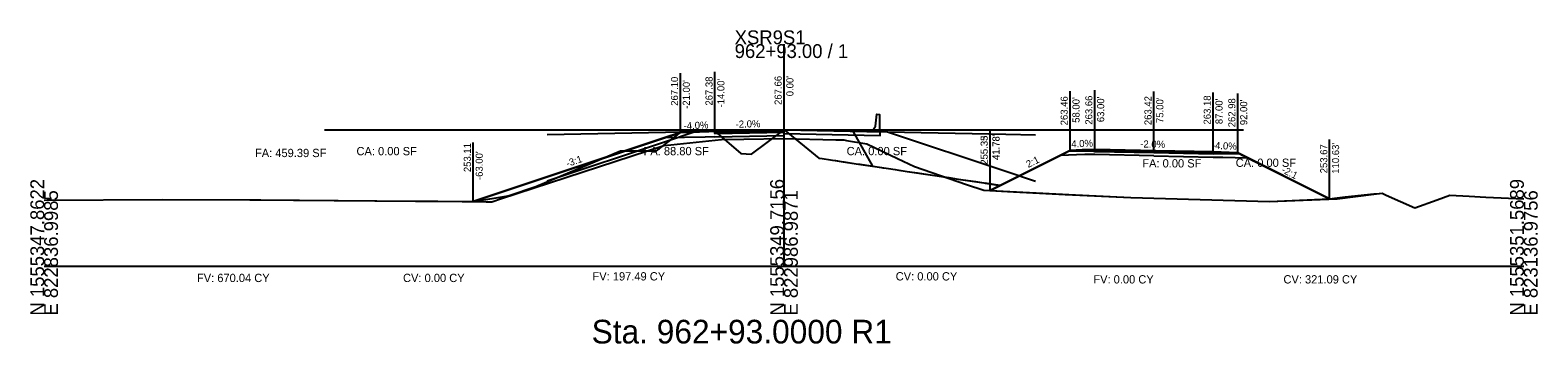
# Model space of a CAD drawing. Extents: x -26 to 823017, y -16 to 1558356.
# Drawn here: x 997.2 to 1302.8, y 1984.3 to 2047.8 of the extents above; entities that cross this region are included whole.
import ezdxf

# ---------------------------------------------------------------- set-up
doc = ezdxf.new("R2010")
doc.units = 0
for name, color, linetype in [('ASPHALT_19MM1', 7, 'Continuous'), ('ASPHALT_9_5MM1', 7, 'Continuous'), ('CONST_DCH', 7, 'Continuous'), ('CONST_LV3', 7, 'Continuous'), ('Default', 7, 'Continuous'), ('Draft_XS_Grid', 7, 'Continuous'), ('Draft_XS_Text', 7, 'Continuous'), ('DTM_CORRIDOR', 7, 'Continuous'), ('DTM_P_FINISHED_GRADE2', 7, 'Continuous'), ('DTM_TEMP_DROP', 7, 'Continuous'), ('DTM_X_GROUND', 7, 'Continuous'), ('PROFILES_DCH_2', 7, 'Continuous'), ('SLOPE_STAKES_FILL', 7, 'Continuous'), ('XS_CELL', 7, 'Continuous'), ('XS_M_SHAPES_EARTHWORK', 7, 'Continuous'), ('XS_P_ASPHALT', 7, 'Continuous'), ('XS_P_CONCRETE', 7, 'Continuous'), ('XS_P_DR_GRAVEL', 7, 'Continuous'), ('XS_P_GROUND', 7, 'Continuous'), ('XS_P_NULL_POINT', 7, 'Continuous'), ('XS_P_SHOULDER', 7, 'Continuous'), ('XS_P_SUBGRADE_GRANULAR', 7, 'Continuous'), ('XS_P_SUBGRADE_MILLING', 7, 'Continuous'), ('XS_P_SUBGRADE_UNDERCUT', 7, 'Continuous'), ('XS_P_TX_CLEARZONE', 7, 'Continuous'), ('XS_P_TX_FS_BS', 7, 'Continuous'), ('XS_SHEET_EW_TX_AREA', 7, 'Continuous'), ('XS_SHEET_EW_TX_VOLUME', 7, 'Continuous')]:
    doc.layers.add(name, color=color, linetype=linetype)

msp = doc.modelspace()

# ---------------------------------------------------------------- linework, layer by layer
at = {"layer": 'ASPHALT_19MM1'}
for points in [[(1150, 2027.37), (1150, 2027.37), (1150, 2027.37), (1136, 2027.09), (1136, 2026.92), (1136, 2026.88), (1150, 2027.16), (1150, 2027.16), (1150, 2027.16)], [(1213, 2023.28), (1225, 2023.04), (1237, 2022.8), (1237, 2023.01), (1225, 2023.25), (1213, 2023.49), (1213, 2023.28)]]:
    msp.add_lwpolyline(points, dxfattribs=at)
at = {"layer": 'ASPHALT_9_5MM1'}
msp.add_lwpolyline([(1150, 2027.66), (1150, 2027.66), (1150, 2027.66), (1136, 2027.38), (1136, 2027.28), (1136, 2027.26), (1150, 2027.54), (1150, 2027.54), (1150, 2027.54)], dxfattribs=at)
at = {"layer": 'CONST_DCH'}
msp.add_lwpolyline([(1213, 2023.49), (1225, 2023.25), (1237, 2023.01), (1237, 2023.18), (1225, 2023.42), (1213, 2023.66), (1213, 2023.49)], dxfattribs=at)
at = {"layer": 'CONST_LV3'}
for points in [[(1056.83, 2027.66), (1059.06, 2027.66), (1067.18, 2027.66), (1070.42, 2027.66), (1077.53, 2027.66), (1081.79, 2027.66), (1087.88, 2027.66), (1092.98, 2027.66), (1098.24, 2027.66), (1102.48, 2027.66), (1108.59, 2027.66), (1115.9, 2027.66), (1118.94, 2027.66), (1127.26, 2027.66), (1129.29, 2027.66), (1130.99, 2027.66), (1139.65, 2027.66), (1140.5, 2027.66), (1150, 2027.66), (1150, 2027.66)], [(1102, 2026.71), (1125.96, 2027.19), (1132, 2027.31), (1146.38, 2027.59), (1150, 2027.67), (1166.77, 2027.33), (1171, 2027.25), (1194.96, 2026.77), (1201, 2026.65)], [(1102, 2017.31), (1125.96, 2025.29), (1132, 2027.31), (1146.38, 2027.59), (1150, 2027.67), (1166.77, 2027.33), (1171, 2027.25), (1194.96, 2019.26), (1201, 2017.25)], [(1150, 2027.66), (1150.59, 2027.66), (1157.45, 2027.66), (1167.49, 2027.66), (1169.32, 2027.66), (1182.33, 2027.66), (1188.64, 2027.66), (1190.46, 2027.66), (1194.72, 2027.66), (1207.35, 2027.66), (1207.96, 2027.66), (1225.43, 2027.66), (1227.27, 2027.66), (1230.92, 2027.66), (1231.99, 2027.66), (1243.17, 2027.67)], [(1150, 2027.67), (1164, 2027.39)], [(1168, 2020.27), (1168, 2020.27), (1164, 2027.39)], [(1191.78, 2015.35), (1207.55, 2023.24), (1208, 2023.46), (1208.15, 2023.47), (1213, 2023.66)], [(1193.78, 2016.35), (1204.72, 2021.82), (1206.38, 2022.65), (1206.57, 2022.74), (1206.59, 2022.75), (1206.9, 2022.91), (1207.36, 2023.14), (1207.36, 2023.14), (1207.37, 2023.14), (1207.4, 2023.16), (1207.4, 2023.16), (1207.42, 2023.17), (1207.55, 2023.24), (1207.57, 2023.24), (1207.58, 2023.25), (1207.66, 2023.29), (1208, 2023.46), (1212.85, 2023.65), (1213, 2023.66), (1213.37, 2023.65), (1225, 2023.42), (1225.37, 2023.41), (1237, 2023.18), (1241.85, 2022.99), (1242, 2022.98), (1242.56, 2022.7), (1242.89, 2022.53), (1243.03, 2022.47), (1243.24, 2022.36), (1243.61, 2022.17), (1244.27, 2021.84), (1246.97, 2020.5), (1260.63, 2013.67), (1262.16, 2013.85), (1263.8, 2014.04), (1269.62, 2014.65), (1270.05, 2014.69), (1271.25, 2014.81), (1272.09, 2014.43), (1277.87, 2011.83), (1282.41, 2013.44), (1284.98, 2014.39), (1288.92, 2014.2), (1292.32, 2014.02), (1300, 2013.65)], [(1242, 2022.98), (1260.69, 2013.64)], [(1000, 2013.38), (1023.98, 2013.54), (1041.69, 2013.47), (1042.31, 2013.47), (1043.91, 2013.45), (1075.27, 2013.21), (1075.69, 2013.21), (1076.41, 2013.2), (1076.55, 2013.2), (1076.76, 2013.2), (1079.81, 2013.17), (1087, 2013.11)]]:
    msp.add_lwpolyline(points, dxfattribs=at)
at = {"layer": 'Default'}
msp.add_lwpolyline([(1150, 2027.54), (1150, 2027.54), (1150, 2027.54), (1136, 2027.26), (1136, 2027.12), (1136, 2027.09), (1150, 2027.37), (1150, 2027.37), (1150, 2027.37)], dxfattribs=at)
at = {"layer": 'DTM_P_FINISHED_GRADE2'}
msp.add_lwpolyline([(1087, 2013.11), (1094.08, 2014.29), (1099.67, 2016.15), (1116.86, 2023.39), (1123.11, 2023.42), (1123.64, 2023.4), (1124.15, 2023.38), (1129, 2027.1), (1134.79, 2027.34), (1136, 2027.38), (1141.26, 2022.83), (1143.41, 2022.73), (1150, 2027.66), (1157.03, 2021.88), (1157.73, 2021.81), (1159.44, 2021.55), (1159.45, 2021.55), (1159.84, 2021.49), (1159.86, 2021.49), (1160.35, 2021.42), (1160.44, 2021.4), (1162, 2021.17), (1162.23, 2021.14), (1164.61, 2020.78), (1165.41, 2020.66), (1169.79, 2020.01), (1170.02, 2019.97), (1170.71, 2019.87), (1171.2, 2019.79), (1172.51, 2019.6), (1173.3, 2019.48), (1174.97, 2019.23), (1177.08, 2018.91), (1180.14, 2018.46), (1180.59, 2018.39), (1181.06, 2018.32), (1183.43, 2017.97), (1185.32, 2017.68), (1188.9, 2017.15), (1190.49, 2016.91), (1190.84, 2016.81), (1193.78, 2016.35), (1193.78, 2016.35)], dxfattribs=at)
at = {"layer": 'DTM_X_GROUND'}
for points in [[(1000, 2013.38), (1023.98, 2013.54), (1041.69, 2013.46), (1042.31, 2013.46), (1043.91, 2013.45), (1075.27, 2013.21), (1075.69, 2013.21), (1076.41, 2013.2), (1076.55, 2013.2), (1076.76, 2013.2), (1079.81, 2013.17), (1087, 2013.11), (1092.95, 2014.1), (1094.02, 2014.28), (1094.08, 2014.29), (1099.67, 2016.15), (1116.86, 2023.39), (1123.11, 2023.42), (1123.64, 2023.4), (1124.15, 2023.38), (1129, 2027.1), (1134.79, 2027.34), (1136, 2027.38), (1141.26, 2022.83), (1143.41, 2022.73), (1150, 2027.66), (1157.03, 2021.88), (1157.73, 2021.81), (1159.44, 2021.55), (1159.45, 2021.55), (1159.84, 2021.49), (1159.86, 2021.49), (1160.35, 2021.42), (1160.44, 2021.4), (1162, 2021.17), (1162.23, 2021.14), (1164.61, 2020.78), (1165.41, 2020.66), (1169.79, 2020.01), (1170.02, 2019.97), (1170.71, 2019.87), (1171.2, 2019.79), (1172.51, 2019.6), (1173.3, 2019.48), (1174.97, 2019.23), (1177.08, 2018.91), (1180.14, 2018.46), (1180.59, 2018.39), (1181.06, 2018.32), (1183.43, 2017.97), (1185.32, 2017.68), (1188.9, 2017.15), (1190.49, 2016.91), (1190.84, 2016.81), (1193.78, 2016.35), (1193.78, 2016.35), (1204.72, 2021.82), (1206.38, 2022.65), (1206.57, 2022.74), (1206.59, 2022.75), (1206.9, 2022.91), (1207.36, 2023.14), (1207.36, 2023.14), (1207.37, 2023.14), (1207.4, 2023.16), (1207.4, 2023.16), (1207.42, 2023.17), (1207.55, 2023.24), (1207.57, 2023.24), (1207.58, 2023.25), (1207.66, 2023.29), (1208, 2023.46), (1212.85, 2023.65), (1213, 2023.66), (1213.37, 2023.65), (1225, 2023.42), (1225.37, 2023.41), (1237, 2023.18), (1241.85, 2022.99), (1242, 2022.98), (1242.56, 2022.7), (1242.89, 2022.53), (1243.03, 2022.47), (1243.24, 2022.36), (1243.61, 2022.17), (1244.27, 2021.84), (1246.97, 2020.5), (1260.63, 2013.67), (1262.16, 2013.85), (1263.8, 2014.04), (1269.62, 2014.65), (1270.05, 2014.69), (1271.25, 2014.81), (1272.09, 2014.43), (1277.87, 2011.83), (1282.41, 2013.44), (1284.98, 2014.39), (1288.92, 2014.2), (1292.32, 2014.02), (1300, 2013.65)], [(1000, 2013.38), (1023.98, 2013.54), (1041.69, 2013.47), (1042.31, 2013.47), (1075.27, 2013.21), (1076.76, 2013.2), (1079.81, 2013.17), (1089.59, 2013.08), (1090.78, 2013.07), (1092.75, 2013.73), (1125.63, 2024.48), (1127.07, 2024.63), (1137.32, 2025.72), (1141.87, 2025.77), (1149.93, 2025.88), (1160.51, 2025.63), (1162.11, 2025.59), (1162.69, 2025.51), (1166.81, 2024.83), (1172.99, 2021.82), (1176.47, 2020.23), (1187, 2016.57), (1190.53, 2015.39), (1196.53, 2015.08), (1207, 2014.55), (1220.32, 2013.96), (1248.41, 2013.13), (1262.16, 2013.67), (1269.62, 2014.61), (1271.25, 2014.81), (1272.09, 2014.43), (1277.87, 2011.83), (1282.41, 2013.44), (1284.98, 2014.39), (1288.92, 2014.2), (1292.32, 2014.02), (1300, 2013.65)], [(1000, 2013.38), (1023.98, 2013.54), (1041.69, 2013.47), (1042.31, 2013.47), (1075.27, 2013.21), (1076.76, 2013.2), (1079.81, 2013.17), (1089.59, 2013.08), (1090.78, 2013.07), (1092.75, 2013.73), (1125.63, 2024.48), (1127.07, 2024.63), (1137.32, 2025.72), (1141.87, 2025.77), (1149.93, 2025.88), (1160.51, 2025.63), (1162.11, 2025.59), (1162.69, 2025.51), (1166.81, 2024.83), (1172.99, 2021.82), (1176.47, 2020.23), (1187, 2016.57), (1190.53, 2015.45), (1191.78, 2015.35), (1206.38, 2022.65), (1206.57, 2022.74), (1206.59, 2022.75), (1207.36, 2023.14), (1207.37, 2023.14), (1207.42, 2023.17), (1207.55, 2023.24), (1208, 2023.46), (1212.85, 2023.65), (1213, 2023.66), (1213.37, 2023.65), (1225, 2023.42), (1225.37, 2023.41), (1237, 2023.18), (1241.85, 2022.99), (1242, 2022.98), (1242.56, 2022.7), (1242.89, 2022.53), (1243.03, 2022.47), (1243.24, 2022.36), (1243.61, 2022.17), (1244.27, 2021.84), (1246.97, 2020.5), (1260.63, 2013.67), (1262.16, 2013.85), (1263.8, 2014.04), (1269.62, 2014.65), (1270.05, 2014.69), (1271.25, 2014.81), (1272.09, 2014.43), (1277.87, 2011.83), (1282.41, 2013.44), (1284.98, 2014.39), (1288.92, 2014.2), (1292.32, 2014.02), (1300, 2013.65)]]:
    msp.add_lwpolyline(points, dxfattribs=at)
at = {"layer": 'XS_CELL'}
for p, q in [((1150, 2000), (1150, 2045)), ((1000, 2000), (1150, 2000)), ((1150, 2000), (1300, 2000))]:
    msp.add_line(p, q, dxfattribs=at)
at = {"layer": 'XS_M_SHAPES_EARTHWORK'}
msp.add_lwpolyline([(1087, 2013.11), (1089.59, 2013.08), (1090.78, 2013.07), (1092.75, 2013.73), (1125.63, 2024.48), (1127.07, 2024.63), (1137.32, 2025.72), (1141.87, 2025.77), (1149.93, 2025.88), (1150, 2025.88), (1150, 2027.16), (1136, 2026.88), (1136, 2026.92), (1136, 2027.09), (1136, 2027.12), (1136, 2027.26), (1136, 2027.28), (1136, 2027.38), (1129, 2027.1), (1125.72, 2026.01)], close=True, dxfattribs=at)
at = {"layer": 'XS_P_CONCRETE'}
for points in [[(1168, 2027.3), (1168, 2027.55), (1168.58, 2028.39), (1168.83, 2030.8), (1169.33, 2030.78), (1169.33, 2027.28), (1168, 2027.3)], [(1150, 2026.91), (1169.5, 2026.52), (1169.5, 2027.27), (1169.33, 2027.28), (1150, 2027.66)]]:
    msp.add_lwpolyline(points, dxfattribs=at)
at = {"layer": 'XS_P_DR_GRAVEL'}
for points in [[(1208.15, 2023.47), (1208, 2023.46), (1207.86, 2023.39), (1207.86, 2023.39), (1212.84, 2023.29), (1213, 2023.28), (1213, 2023.3), (1213, 2023.66), (1208.15, 2023.47)], [(1241.85, 2022.99), (1242, 2022.98), (1242.56, 2022.7), (1242.57, 2022.69), (1242.4, 2022.7), (1237, 2022.8), (1237, 2022.82), (1237, 2023.18), (1241.85, 2022.99)]]:
    msp.add_lwpolyline(points, dxfattribs=at)
at = {"layer": 'XS_P_GROUND'}
for points in [[(1087, 2013.11), (1129, 2027.1)], [(1157.73, 2021.81), (1159.44, 2021.55), (1159.84, 2021.49), (1160.35, 2021.42), (1162, 2021.17), (1164.61, 2020.78), (1168.4, 2020.21), (1169.79, 2020.01), (1170.71, 2019.87), (1172.51, 2019.6), (1174.97, 2019.23), (1180.14, 2018.46), (1181.06, 2018.32), (1185.32, 2017.68), (1190.49, 2016.91), (1190.81, 2016.86)], [(1208, 2023.46), (1191.78, 2015.35)], [(1242, 2022.98), (1260.63, 2013.67)], [(1193.78, 2016.38), (1190.81, 2016.86)]]:
    msp.add_lwpolyline(points, dxfattribs=at)
at = {"layer": 'XS_P_SHOULDER'}
for points in [[(1129, 2027.1), (1136, 2027.38)], [(1208, 2023.46), (1208.15, 2023.47), (1213, 2023.66)], [(1242, 2022.98), (1241.85, 2022.99), (1237, 2023.18)]]:
    msp.add_lwpolyline(points, dxfattribs=at)
at = {"layer": 'XS_P_SUBGRADE_GRANULAR'}
for points in [[(1136, 2026.22), (1134, 2026.18), (1125.72, 2026.01)], [(1136, 2026.22), (1150, 2026.5), (1150, 2026.5)], [(1213, 2022.62), (1211, 2022.66), (1206, 2022.46)], [(1225, 2022.38), (1213, 2022.62)], [(1225, 2022.38), (1237, 2022.14)], [(1237, 2022.14), (1239, 2022.1), (1243.96, 2022)]]:
    msp.add_lwpolyline(points, dxfattribs=at)
at = {"layer": 'XS_P_SUBGRADE_UNDERCUT'}
msp.add_lwpolyline([(1209.11, 2014.47), (1220.32, 2013.96), (1248.41, 2013.13), (1260.63, 2013.67), (1242, 2022.98), (1241.26, 2023.01), (1237, 2023.18), (1225.37, 2023.41), (1213, 2023.66), (1210.42, 2023.56), (1208, 2023.46), (1191.78, 2015.35)], close=True, dxfattribs=at)
at = {"layer": 'XS_P_TX_CLEARZONE'}
for p, q in [((1129, 2027.1), (1129, 2039.1)), ((1136, 2027.38), (1136, 2039.38)), ((1150, 2027.66), (1150, 2039.66)), ((1208, 2023.46), (1208, 2035.46)), ((1213, 2023.66), (1213, 2035.66)), ((1225, 2023.42), (1225, 2035.42)), ((1237, 2023.18), (1237, 2035.18)), ((1242, 2022.98), (1242, 2034.98)), ((1191.78, 2015.35), (1191.78, 2027.35)), ((1191.78, 2015.33), (1191.78, 2027.33)), ((1087, 2013.11), (1087, 2025.11)), ((1260.63, 2013.67), (1260.63, 2025.67))]:
    msp.add_line(p, q, dxfattribs=at)

# ---------------------------------------------------------------- texts
at = {"layer": 'CONST_DCH'}
for p in [(1191.71, 2015.23), (1260.55, 2013.55), (1260.61, 2013.52)]:
    msp.add_text('X', height=0.24, dxfattribs=at).set_placement(p)
at = {"layer": 'Draft_XS_Grid'}
msp.add_text('-', height=0.0001, dxfattribs=at).set_placement((1000, 2000))
at = {"layer": 'Draft_XS_Text'}
msp.add_text('Sta. 962+93.0000 R1', height=4.8, dxfattribs=at).set_placement((1111, 1984.35))
at = {"layer": 'DTM_CORRIDOR'}
for p in [(1212.92, 2023.54), (1224.92, 2023.3), (1236.92, 2023.06)]:
    msp.add_text('X', height=0.24, dxfattribs=at).set_placement(p)
at = {"layer": 'DTM_TEMP_DROP'}
for p in [(1135.92, 2027.26), (1149.92, 2027.54), (1157.65, 2021.69), (1191.71, 2015.21)]:
    msp.add_text('X', height=0.24, dxfattribs=at).set_placement(p)
at = {"layer": 'PROFILES_DCH_2'}
msp.add_text('X', height=0.24, dxfattribs=at).set_placement((1167.92, 2020.15))
at = {"layer": 'SLOPE_STAKES_FILL'}
for p in [(1193.7, 2016.26), (1086.92, 2012.99)]:
    msp.add_text('X', height=0.24, dxfattribs=at).set_placement(p)
at = {"layer": 'XS_CELL'}
for s, p in [('XSR9S1', (1140, 2045)), ('962+93.00 / 1', (1140, 2042.2))]:
    msp.add_text(s, height=2.8, dxfattribs=at).set_placement(p)
for s, p in [('N 1555347.8622', (1000, 1990)), ('N 1555349.7156', (1150, 1990)), ('N 1555351.5689', (1300, 1990)), ('E 822836.9985', (1002.8, 1990)), ('E 822986.9871', (1152.8, 1990)), ('E 823136.9756', (1302.8, 1990))]:
    msp.add_text(s, height=2.8, rotation=90, dxfattribs=at).set_placement(p)
at = {"layer": 'XS_P_ASPHALT'}
for p in [(1191.71, 2015.23), (1260.55, 2013.55)]:
    msp.add_text('X', height=0.24, dxfattribs=at).set_placement(p)
at = {"layer": 'XS_P_NULL_POINT'}
msp.add_text('X', height=0.24, dxfattribs=at).set_placement((1086.92, 2012.99))
at = {"layer": 'XS_P_SHOULDER'}
for p in [(1207.92, 2023.34), (1241.92, 2022.86)]:
    msp.add_text('X', height=0.24, dxfattribs=at).set_placement(p)
at = {"layer": 'XS_P_SUBGRADE_MILLING'}
msp.add_text('X', height=0.24, dxfattribs=at).set_placement((1128.92, 2026.98))
at = {"layer": 'XS_P_TX_CLEARZONE'}
for s, p in [('267.10', (1128.52, 2032.52)), ("-21.00'", (1130.92, 2031.9)), ('267.38', (1135.52, 2032.56)), ("-14.00'", (1137.92, 2032.18)), ('267.66', (1149.52, 2032.69)), ("0.00'", (1151.92, 2034.45)), ('263.46', (1207.52, 2028.56)), ("58.00'", (1209.92, 2029.07)), ('263.66', (1212.52, 2028.69)), ("63.00'", (1214.92, 2029.2)), ('263.42', (1224.52, 2028.6)), ("75.00'", (1226.92, 2029.03)), ('263.18', (1236.52, 2028.72)), ("87.00'", (1238.92, 2028.79)), ('262.98', (1241.52, 2028.16)), ("92.00'", (1243.92, 2028.59)), ('253.11', (1086.52, 2019.08)), ('255.35', (1191.3, 2020.6)), ('255.33', (1191.3, 2020.57)), ("41.78'", (1193.7, 2021.55)), ("41.78'", (1193.7, 2021.52)), ('253.67', (1260.15, 2018.84)), ("110.63'", (1262.55, 2018.75)), ("-63.00'", (1088.92, 2017.47))]:
    msp.add_text(s, height=1.44, rotation=90, dxfattribs=at).set_placement(p)
at = {"layer": 'XS_P_TX_FS_BS'}
for s, rotation, p in [('-4.0%', 2.2906, (1129.68, 2027.73)), ('-2.0%', 1.1458, (1140.2, 2028.07)), ('4.0%', 2.2906, (1208.27, 2024.07)), ('-2.0%', 358.8542, (1222.22, 2024.08)), ('-4.0%', 357.7094, (1236.73, 2023.79)), ('-3:1', 18.4332, (1106.09, 2020.1)), ('2:1', 26.4819, (1199.53, 2019.91)), ('-2:1', 333.4349, (1250.74, 2019.09))]:
    msp.add_text(s, height=1.44, rotation=rotation, dxfattribs=at).set_placement(p)
at = {"layer": 'XS_SHEET_EW_TX_AREA'}
for s, p in [('FA: 459.39 SF', (1042.74, 2022.12)), ('CA: 0.00 SF', (1063.32, 2022.49)), ('FA: 88.80 SF', (1121.53, 2022.5)), ('CA: 0.00 SF', (1162.7, 2022.5)), ('FA: 0.00 SF', (1222.64, 2020.02)), ('CA: 0.00 SF', (1241.58, 2020.14))]:
    msp.add_text(s, height=1.68, dxfattribs=at).set_placement(p)
at = {"layer": 'XS_SHEET_EW_TX_VOLUME'}
for s, p in [('FV: 670.04 CY', (1030.98, 1996.8)), ('CV: 0.00 CY', (1072.76, 1996.8)), ('FV: 197.49 CY', (1111.17, 1997.12)), ('CV: 0.00 CY', (1172.65, 1997.12)), ('FV: 0.00 CY', (1212.72, 1996.51)), ('CV: 321.09 CY', (1251.26, 1996.51))]:
    msp.add_text(s, height=1.68, dxfattribs=at).set_placement(p)

doc.saveas('drawing.dxf')
